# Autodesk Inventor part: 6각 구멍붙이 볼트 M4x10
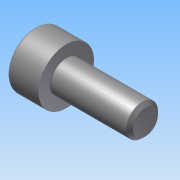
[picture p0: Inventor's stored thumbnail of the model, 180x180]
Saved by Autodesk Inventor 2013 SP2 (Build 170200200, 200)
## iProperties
Created: 2026-07
Part Number: 6각 구멍붙이 볼트 M4x10
Material: Generic
Document SubType Name: Modeling
Designer: aa
Density: 1 g/cm^3
변환 표준: STEP AP214IS
전처리기: Build: 200, Release: 2013 SP2 Update 6 - Date: Thu 07/17/2014
전송 단위: 밀리미터
불확실성: 0.01
Author: aa
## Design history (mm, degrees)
node "6각 구멍붙이 볼트 M4x101"
body "Solid1"
node "기준1"
